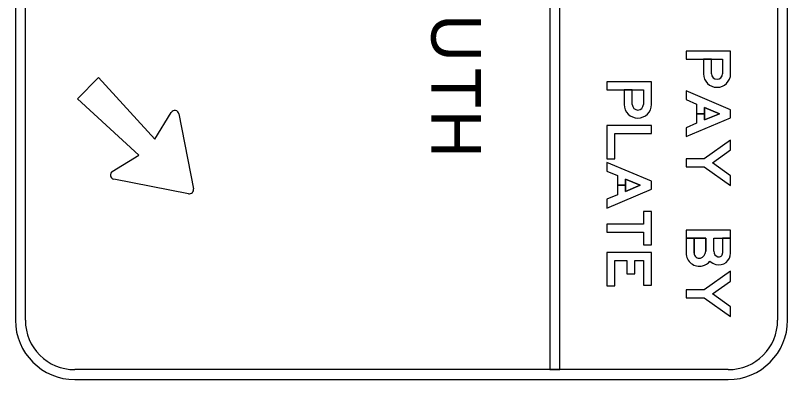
# Model space of a CAD drawing. Extents: x -830008.4 to -829992.7, y 1290284.1 to 1290294.4.
# Drawn here: x -830004.537 to -830003.757, y 1290287.657 to 1290288.025 of the extents above; entities that cross this region are included whole.
import ezdxf

# ---------------------------------------------------------------- set-up
doc = ezdxf.new("R2010")
doc.units = 0
doc.layers.add('SignPanel', color=7, linetype='Continuous')

msp = doc.modelspace()

# ---------------------------------------------------------------- linework, layer by layer
at = {"layer": 'SignPanel'}
for p, q in [((-830003.99691, 1290288.57729), (-830003.99691, 1290287.66729)), ((-830003.98691, 1290287.66729), (-830003.98691, 1290288.57729)), ((-830003.76691, 1290288.52729), (-830003.76691, 1290287.71729)), ((-830003.75691, 1290287.71729), (-830003.75691, 1290288.52729)), ((-830004.53691, 1290288.52719), (-830004.53691, 1290287.71729)), ((-830004.52691, 1290287.71729), (-830004.52691, 1290288.52719)), ((-830003.84186, 1290287.98069), (-830003.84186, 1290287.96607)), ((-830003.82251, 1290287.98069), (-830003.82251, 1290287.96607)), ((-830003.82251, 1290287.98069), (-830003.82251, 1290287.96607)), ((-830003.82251, 1290287.98069), (-830003.82251, 1290287.96607)), ((-830003.92186, 1290287.94969), (-830003.92186, 1290287.93507)), ((-830003.90251, 1290287.94969), (-830003.90251, 1290287.93507)), ((-830003.90251, 1290287.94969), (-830003.90251, 1290287.93507)), ((-830003.90251, 1290287.94969), (-830003.90251, 1290287.93507)), ((-830003.85941, 1290287.80819), (-830003.85941, 1290287.78502)), ((-830003.81691, 1290287.66729), (-830004.47691, 1290287.66729)), ((-830003.99691, 1290287.66729), (-830003.98691, 1290287.66729)), ((-830004.47691, 1290287.65729), (-830003.81691, 1290287.65729))]:
    msp.add_line(p, q, dxfattribs=at)
for points in [[(-830003.81441, 1290287.96607), (-830003.81441, 1290287.98879), (-830003.85941, 1290287.98879), (-830003.85941, 1290287.98069), (-830003.84186, 1290287.98069)], [(-830003.81441, 1290287.96607), (-830003.81441, 1290287.98879), (-830003.85941, 1290287.98879), (-830003.85941, 1290287.98069), (-830003.82251, 1290287.98069)], [(-830003.81441, 1290287.96607), (-830003.81441, 1290287.98879), (-830003.85941, 1290287.98879), (-830003.85941, 1290287.98069), (-830003.82251, 1290287.98069)], [(-830003.83376, 1290287.96607), (-830003.83376, 1290287.98069), (-830003.84186, 1290287.98069), (-830003.84186, 1290287.96607)], [(-830003.83376, 1290287.96607), (-830003.83376, 1290287.98069), (-830003.84186, 1290287.98069), (-830003.84186, 1290287.96607)], [(-830003.83376, 1290287.96607), (-830003.83376, 1290287.98069), (-830003.82251, 1290287.98069)], [(-830004.43903, 1290287.86742), (-830004.41217, 1290287.88388), (-830004.47437, 1290287.94085), (-830004.45294, 1290287.96228), (-830004.39596, 1290287.90008), (-830004.37951, 1290287.92694)], [(-830003.89441, 1290287.93507), (-830003.89441, 1290287.95779), (-830003.93941, 1290287.95779), (-830003.93941, 1290287.94969), (-830003.92186, 1290287.94969)], [(-830003.89441, 1290287.93507), (-830003.89441, 1290287.95779), (-830003.93941, 1290287.95779), (-830003.93941, 1290287.94969), (-830003.90251, 1290287.94969)], [(-830003.89441, 1290287.93507), (-830003.89441, 1290287.95779), (-830003.93941, 1290287.95779), (-830003.93941, 1290287.94969), (-830003.90251, 1290287.94969)], [(-830003.91376, 1290287.93507), (-830003.91376, 1290287.94969), (-830003.92186, 1290287.94969), (-830003.92186, 1290287.93507)], [(-830003.91376, 1290287.93507), (-830003.91376, 1290287.94969), (-830003.92186, 1290287.94969), (-830003.92186, 1290287.93507)], [(-830003.91376, 1290287.93507), (-830003.91376, 1290287.94969), (-830003.90251, 1290287.94969)], [(-830004.37169, 1290287.92553), (-830004.35703, 1290287.84994)], [(-830004.36203, 1290287.84494), (-830004.43762, 1290287.85961)], [(-830003.81441, 1290287.78502), (-830003.81441, 1290287.80819), (-830003.85941, 1290287.80819)], [(-830003.83151, 1290287.78676), (-830003.83151, 1290287.80009), (-830003.81441, 1290287.80009), (-830003.81441, 1290287.80819), (-830003.85941, 1290287.80819), (-830003.85941, 1290287.80009)], [(-830003.83151, 1290287.78676), (-830003.83151, 1290287.80009), (-830003.81441, 1290287.80009), (-830003.81441, 1290287.80819), (-830003.85941, 1290287.80819), (-830003.85941, 1290287.80009)], [(-830003.85941, 1290287.80009), (-830003.83961, 1290287.80009), (-830003.83961, 1290287.78676)], [(-830003.85131, 1290287.78502), (-830003.85131, 1290287.80009), (-830003.85941, 1290287.80009), (-830003.85941, 1290287.78502)], [(-830003.85941, 1290287.80009), (-830003.83961, 1290287.80009), (-830003.83961, 1290287.78676)], [(-830003.85131, 1290287.78502), (-830003.85131, 1290287.80009), (-830003.85941, 1290287.80009), (-830003.85941, 1290287.78502)], [(-830003.83961, 1290287.78676), (-830003.83961, 1290287.80009), (-830003.85131, 1290287.80009), (-830003.85131, 1290287.78502)], [(-830003.83151, 1290287.78676), (-830003.83151, 1290287.80009), (-830003.82251, 1290287.80009), (-830003.82251, 1290287.78502)], [(-830003.81441, 1290287.78502), (-830003.81441, 1290287.80009), (-830003.82251, 1290287.80009), (-830003.82251, 1290287.78502)], [(-830003.81441, 1290287.78502), (-830003.81441, 1290287.80009), (-830003.82251, 1290287.80009), (-830003.82251, 1290287.78502)]]:
    msp.add_lwpolyline(points, dxfattribs=at)
for points in [[(-830003.84884, 1290287.93544), (-830003.84884, 1290287.91599), (-830003.85941, 1290287.91155), (-830003.85941, 1290287.90277), (-830003.81441, 1290287.92167), (-830003.81441, 1290287.92977), (-830003.85941, 1290287.94867), (-830003.85941, 1290287.93988)], [(-830003.84074, 1290287.9194), (-830003.84074, 1290287.92571), (-830003.84884, 1290287.92571), (-830003.84884, 1290287.91599), (-830003.85941, 1290287.91155), (-830003.85941, 1290287.90277), (-830003.81441, 1290287.92167), (-830003.81441, 1290287.92977), (-830003.85941, 1290287.94867), (-830003.85941, 1290287.93988), (-830003.84884, 1290287.93544), (-830003.84884, 1290287.92572), (-830003.84074, 1290287.92572), (-830003.84074, 1290287.93204), (-830003.82569, 1290287.92572)], [(-830003.84074, 1290287.9194), (-830003.84074, 1290287.92571), (-830003.84884, 1290287.92571), (-830003.84884, 1290287.91599), (-830003.85941, 1290287.91155), (-830003.85941, 1290287.90277), (-830003.81441, 1290287.92167), (-830003.81441, 1290287.92977), (-830003.85941, 1290287.94867), (-830003.85941, 1290287.93988), (-830003.84884, 1290287.93544), (-830003.84884, 1290287.92572), (-830003.84074, 1290287.92572), (-830003.84074, 1290287.93204), (-830003.82569, 1290287.92572)], [(-830003.84074, 1290287.9194), (-830003.82569, 1290287.92572), (-830003.84074, 1290287.93204)], [(-830003.93941, 1290287.87998), (-830003.93154, 1290287.87998), (-830003.93154, 1290287.90563), (-830003.89441, 1290287.90563), (-830003.89441, 1290287.91372), (-830003.93941, 1290287.91372)], [(-830003.93941, 1290287.87998), (-830003.93154, 1290287.87998), (-830003.93154, 1290287.90563), (-830003.89441, 1290287.90563), (-830003.89441, 1290287.91372), (-830003.93941, 1290287.91372)], [(-830003.93941, 1290287.87998), (-830003.93154, 1290287.87998), (-830003.93154, 1290287.90563), (-830003.89441, 1290287.90563), (-830003.89441, 1290287.91372), (-830003.93941, 1290287.91372)], [(-830003.84119, 1290287.87209), (-830003.81441, 1290287.85319), (-830003.81441, 1290287.86311), (-830003.83288, 1290287.87614), (-830003.81441, 1290287.88918), (-830003.81441, 1290287.89909), (-830003.84119, 1290287.88019), (-830003.85941, 1290287.88019), (-830003.85941, 1290287.87209)], [(-830003.84119, 1290287.87209), (-830003.81441, 1290287.85319), (-830003.81441, 1290287.86311), (-830003.83288, 1290287.87614), (-830003.81441, 1290287.88918), (-830003.81441, 1290287.89909), (-830003.84119, 1290287.88019), (-830003.85941, 1290287.88019), (-830003.85941, 1290287.87209)], [(-830003.84119, 1290287.87209), (-830003.81441, 1290287.85319), (-830003.81441, 1290287.86311), (-830003.83288, 1290287.87614), (-830003.81441, 1290287.88918), (-830003.81441, 1290287.89909), (-830003.84119, 1290287.88019), (-830003.85941, 1290287.88019), (-830003.85941, 1290287.87209)], [(-830003.92884, 1290287.86316), (-830003.92884, 1290287.84372), (-830003.93941, 1290287.83928), (-830003.93941, 1290287.83049), (-830003.89441, 1290287.84939), (-830003.89441, 1290287.85749), (-830003.93941, 1290287.87639), (-830003.93941, 1290287.86761)], [(-830003.92074, 1290287.84712), (-830003.92074, 1290287.85344), (-830003.92884, 1290287.85344), (-830003.92884, 1290287.84372), (-830003.93941, 1290287.83928), (-830003.93941, 1290287.83049), (-830003.89441, 1290287.84939), (-830003.89441, 1290287.85749), (-830003.93941, 1290287.87639), (-830003.93941, 1290287.86761), (-830003.92884, 1290287.86316), (-830003.92884, 1290287.85344), (-830003.92074, 1290287.85344), (-830003.92074, 1290287.85976), (-830003.90569, 1290287.85344)], [(-830003.92074, 1290287.84712), (-830003.92074, 1290287.85344), (-830003.92884, 1290287.85344), (-830003.92884, 1290287.84372), (-830003.93941, 1290287.83928), (-830003.93941, 1290287.83049), (-830003.89441, 1290287.84939), (-830003.89441, 1290287.85749), (-830003.93941, 1290287.87639), (-830003.93941, 1290287.86761), (-830003.92884, 1290287.86316), (-830003.92884, 1290287.85344), (-830003.92074, 1290287.85344), (-830003.92074, 1290287.85976), (-830003.90569, 1290287.85344)], [(-830003.92074, 1290287.84712), (-830003.90569, 1290287.85344), (-830003.92074, 1290287.85976)], [(-830003.90251, 1290287.82691), (-830003.90251, 1290287.81408), (-830003.93941, 1290287.81408), (-830003.93941, 1290287.80598), (-830003.90251, 1290287.80598), (-830003.90251, 1290287.79316), (-830003.89441, 1290287.79316), (-830003.89441, 1290287.82691)], [(-830003.90251, 1290287.82691), (-830003.90251, 1290287.81408), (-830003.93941, 1290287.81408), (-830003.93941, 1290287.80598), (-830003.90251, 1290287.80598), (-830003.90251, 1290287.79316), (-830003.89441, 1290287.79316), (-830003.89441, 1290287.82691)], [(-830003.90251, 1290287.82691), (-830003.90251, 1290287.81408), (-830003.93941, 1290287.81408), (-830003.93941, 1290287.80598), (-830003.90251, 1290287.80598), (-830003.90251, 1290287.79316), (-830003.89441, 1290287.79316), (-830003.89441, 1290287.82691)], [(-830003.93131, 1290287.75179), (-830003.93131, 1290287.77744), (-830003.91921, 1290287.77744), (-830003.91921, 1290287.76417), (-830003.91111, 1290287.76417), (-830003.91111, 1290287.77744), (-830003.90251, 1290287.77744), (-830003.90251, 1290287.75247), (-830003.89441, 1290287.75247), (-830003.89441, 1290287.78554), (-830003.93941, 1290287.78554), (-830003.93941, 1290287.75179)], [(-830003.93131, 1290287.75179), (-830003.93131, 1290287.77744), (-830003.91921, 1290287.77744), (-830003.91921, 1290287.76417), (-830003.91111, 1290287.76417), (-830003.91111, 1290287.77744), (-830003.90251, 1290287.77744), (-830003.90251, 1290287.75247), (-830003.89441, 1290287.75247), (-830003.89441, 1290287.78554), (-830003.93941, 1290287.78554), (-830003.93941, 1290287.75179)], [(-830003.93131, 1290287.75179), (-830003.93131, 1290287.77744), (-830003.91921, 1290287.77744), (-830003.91921, 1290287.76417), (-830003.91111, 1290287.76417), (-830003.91111, 1290287.77744), (-830003.90251, 1290287.77744), (-830003.90251, 1290287.75247), (-830003.89441, 1290287.75247), (-830003.89441, 1290287.78554), (-830003.93941, 1290287.78554), (-830003.93941, 1290287.75179)], [(-830003.84119, 1290287.73969), (-830003.81441, 1290287.72079), (-830003.81441, 1290287.73071), (-830003.83288, 1290287.74374), (-830003.81441, 1290287.75678), (-830003.81441, 1290287.76669), (-830003.84119, 1290287.74779), (-830003.85941, 1290287.74779), (-830003.85941, 1290287.73969)], [(-830003.84119, 1290287.73969), (-830003.81441, 1290287.72079), (-830003.81441, 1290287.73071), (-830003.83288, 1290287.74374), (-830003.81441, 1290287.75678), (-830003.81441, 1290287.76669), (-830003.84119, 1290287.74779), (-830003.85941, 1290287.74779), (-830003.85941, 1290287.73969)], [(-830003.84119, 1290287.73969), (-830003.81441, 1290287.72079), (-830003.81441, 1290287.73071), (-830003.83288, 1290287.74374), (-830003.81441, 1290287.75678), (-830003.81441, 1290287.76669), (-830003.84119, 1290287.74779), (-830003.85941, 1290287.74779), (-830003.85941, 1290287.73969)]]:
    msp.add_lwpolyline(points, close=True, dxfattribs=at)
for centre, radius, start, end in [((-830004.37588, 1290287.92472), 0.00426, 10.97773, 148.51547), ((-830004.43681, 1290287.86379), 0.00426, 121.48453, 259.02227), ((-830004.36121, 1290287.84913), 0.00426, 259.02227, 10.97773), ((-830004.47691, 1290287.71729), 0.06, 180, 270), ((-830004.47691, 1290287.71729), 0.05, 180, 270), ((-830003.81691, 1290287.71729), 0.06, 270, 0), ((-830003.81691, 1290287.71729), 0.05, 270, 0)]:
    msp.add_arc(centre, radius, start, end, dxfattribs=at)
for centre, major_axis, ratio, start_param, end_param in [((-830003.82814, 1290287.96607), (0.01373, 0), 0.999995, 3.141593, 6.283185), ((-830003.82814, 1290287.96607), (0.01373, 0), 0.999995, 3.141593, 6.283185), ((-830003.82814, 1290287.96607), (0.01373, 0), 0.999995, 3.141593, 6.283185), ((-830003.82814, 1290287.96607), (0.00563, 0), 0.999995, 3.141593, 6.283185), ((-830003.82814, 1290287.96607), (0.00563, 0), 0.999995, 3.141593, 6.283185), ((-830003.82814, 1290287.96607), (0.00563, 0), 0.999995, 3.141593, 6.283185), ((-830003.90814, 1290287.93507), (0.01373, 0), 0.999995, 3.141593, 6.283185), ((-830003.90814, 1290287.93507), (0.01373, 0), 0.999995, 3.141593, 6.283185), ((-830003.90814, 1290287.93507), (0.01373, 0), 0.999995, 3.141593, 6.283185), ((-830003.90814, 1290287.93507), (0.00563, 0), 0.999995, 3.141593, 6.283185), ((-830003.90814, 1290287.93507), (0.00563, 0), 0.999995, 3.141593, 6.283185), ((-830003.90814, 1290287.93507), (0.00563, 0), 0.999995, 3.141593, 6.283185), ((-830003.84659, 1290287.78676), (0.00698, 0), 0.999999, 4.965069, 6.283185), ((-830003.84659, 1290287.78676), (0.00698, 0), 0.999999, 4.965069, 6.283185), ((-830003.84659, 1290287.78676), (0.00698, 0), 0.999999, 4.965069, 6.283185), ((-830003.82589, 1290287.78676), (0.00563, 0), 0.999999, 3.141593, 4.459709), ((-830003.82589, 1290287.78676), (0.00563, 0), 0.999999, 3.141593, 4.459709), ((-830003.82589, 1290287.78676), (0.00563, 0), 0.999999, 3.141593, 4.459709), ((-830003.84614, 1290287.78502), (0.01328, 0), 0.999999, 3.141593, 4.965069), ((-830003.84614, 1290287.78502), (0.01328, 0), 0.999999, 3.141593, 4.965069), ((-830003.84614, 1290287.78502), (0.01328, 0), 0.999999, 3.141593, 4.965069), ((-830003.84614, 1290287.78502), (0.00518, 0), 0.999999, 3.141593, 4.965069), ((-830003.84614, 1290287.78502), (0.00518, 0), 0.999999, 3.141593, 4.965069), ((-830003.84614, 1290287.78502), (0.00518, 0), 0.999999, 3.141593, 4.965069), ((-830003.82634, 1290287.78502), (0.01193, 0), 0.999999, 4.459709, 6.283185), ((-830003.82634, 1290287.78502), (0.01193, 0), 0.999999, 4.459709, 6.283185), ((-830003.82634, 1290287.78502), (0.01193, 0), 0.999999, 4.459709, 6.283185), ((-830003.82634, 1290287.78502), (0.00383, 0), 0.999999, 4.459709, 6.283185), ((-830003.82634, 1290287.78502), (0.00383, 0), 0.999999, 4.459709, 6.283185), ((-830003.82634, 1290287.78502), (0.00383, 0), 0.999999, 4.459709, 6.283185), ((-830003.84659, 1290287.78676), (0.01508, 0), 0.999999, 4.965069, 5.558736), ((-830003.84659, 1290287.78676), (0.01508, 0), 0.999999, 4.965069, 5.558736), ((-830003.84659, 1290287.78676), (0.01508, 0), 0.999999, 4.965069, 5.558736), ((-830003.82589, 1290287.78676), (0.01373, 0), 0.999999, 3.95686, 4.459709), ((-830003.82589, 1290287.78676), (0.01373, 0), 0.999999, 3.95686, 4.459709), ((-830003.82589, 1290287.78676), (0.01373, 0), 0.999999, 3.95686, 4.459709)]:
    msp.add_ellipse(centre, major_axis=major_axis, ratio=ratio, start_param=start_param, end_param=end_param, dxfattribs=at)

# ---------------------------------------------------------------- texts
for s, p in [('U', (-830004.11674, 1290288.02631)), ('T', (-830004.11674, 1290287.97196)), ('H', (-830004.11674, 1290287.92951))]:
    msp.add_text(s, height=0.05, rotation=270, dxfattribs=at).set_placement(p)

doc.saveas('drawing.dxf')
